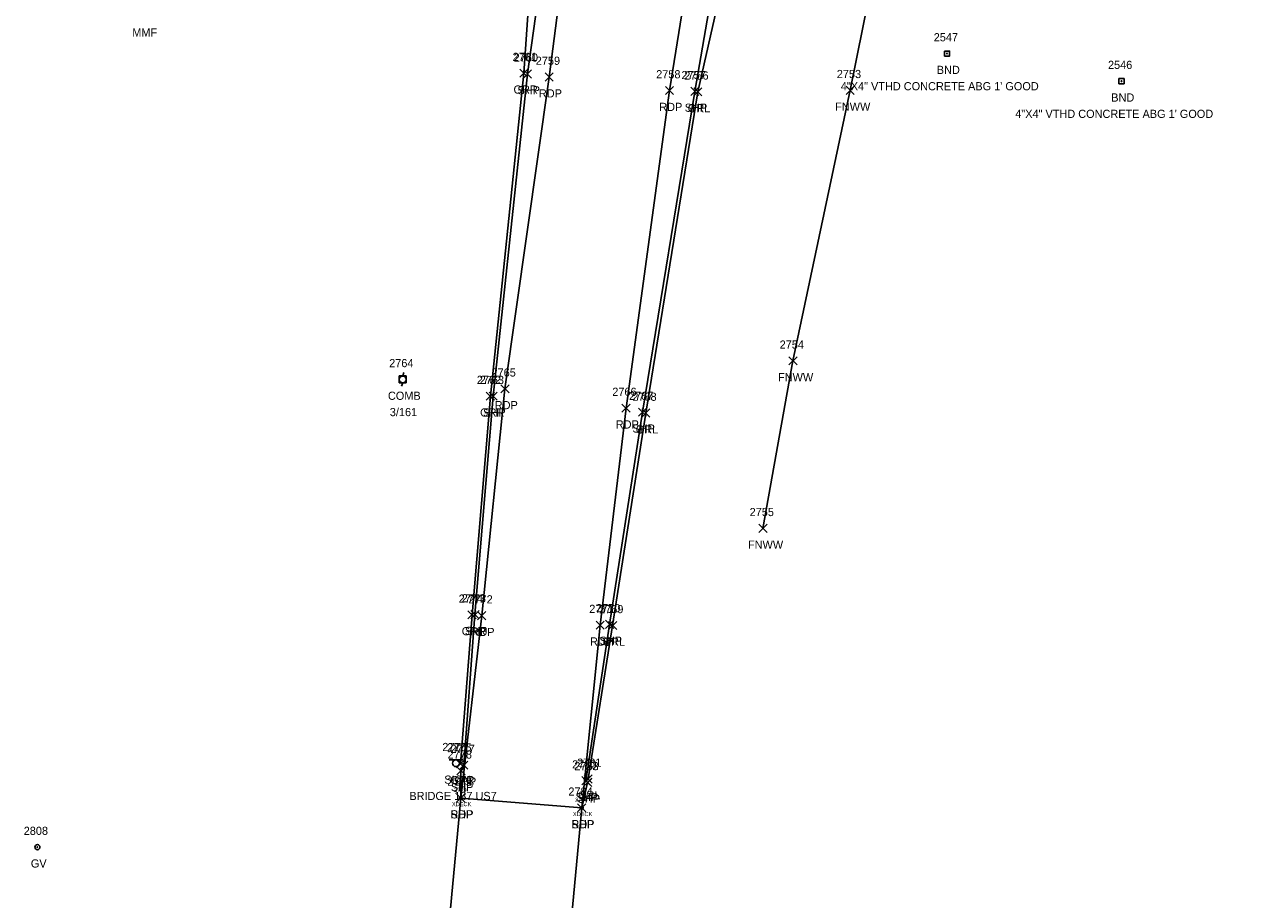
# Model space of a CAD drawing. Extents: x 1443071 to 1445292, y 614024 to 622563.
# Drawn here: x 1443936.5 to 1444233.7, y 619891.2 to 620105.8 of the extents above; entities that cross this region are included whole.
import ezdxf

# ---------------------------------------------------------------- set-up
doc = ezdxf.new("R2010")
doc.units = 0
for name, color, linetype in [('B_A', 7, 'Continuous'), ('B_I', 7, 'Continuous'), ('B_TIC', 7, 'Continuous'), ('BELB', 7, 'Continuous'), ('L_A', 7, 'Continuous'), ('L_I', 7, 'Continuous'), ('L_TIC', 7, 'Continuous'), ('LFNC', 7, 'Continuous'), ('M_A', 7, 'Continuous'), ('M_C', 7, 'Continuous'), ('M_I', 7, 'Continuous'), ('MHBP', 7, 'Continuous'), ('P_A', 7, 'Continuous'), ('P_I', 7, 'Continuous'), ('P_TIC', 7, 'Continuous'), ('PET', 7, 'Continuous'), ('PSP', 7, 'Continuous'), ('R_A', 7, 'Continuous'), ('R_I', 7, 'Continuous'), ('R_TIC', 7, 'Continuous'), ('RGR', 7, 'Continuous'), ('S_A', 7, 'Continuous'), ('S_C', 7, 'Continuous'), ('S_I', 7, 'Continuous'), ('SSGN', 7, 'Continuous'), ('U_A', 7, 'Continuous'), ('U_C', 7, 'Continuous'), ('U_I', 7, 'Continuous'), ('UP', 7, 'Continuous'), ('UWV', 7, 'Continuous')]:
    doc.layers.add(name, color=color, linetype=linetype)

msp = doc.modelspace()

# ---------------------------------------------------------------- linework, layer by layer
at = {"layer": 'B_TIC'}
for p, q in [((1444043.42, 619916.17), (1444043.5, 619916.17)), ((1444073.06, 619913.75), (1444073.13, 619913.75))]:
    msp.add_line(p, q, dxfattribs=at)
for points in [[(1444042.92, 619916.17), (1444043.92, 619916.17)], [(1444043.42, 619915.67), (1444043.42, 619916.67)], [(1444072.55, 619913.75), (1444073.55, 619913.75)], [(1444073.05, 619913.25), (1444073.05, 619914.25)]]:
    msp.add_lwpolyline(points, dxfattribs=at)
at = {"layer": 'BELB'}
for points in [[(1444043.42, 619916.17), (1444038.87, 619867.29), (1444033.97, 619808.54), (1444030.6, 619759.6)], [(1444073.05, 619913.75), (1444068.55, 619864.95), (1444063.61, 619806.17), (1444060.23, 619757.24)]]:
    msp.add_lwpolyline(points, dxfattribs=at)
at = {"layer": 'L_TIC'}
for points in [[(1444137.8, 620088.58), (1444139.8, 620090.58)], [(1444139.8, 620088.58), (1444137.8, 620090.58)], [(1444123.8, 620022.28), (1444125.8, 620024.28)], [(1444125.8, 620022.28), (1444123.8, 620024.28)], [(1444116.45, 619981.25), (1444118.45, 619983.25)], [(1444118.45, 619981.25), (1444116.45, 619983.25)]]:
    msp.add_lwpolyline(points, dxfattribs=at)
at = {"layer": 'LFNC'}
msp.add_lwpolyline([(1444167.73, 620231.87), (1444148.34, 620136.96), (1444138.8, 620089.58), (1444124.8, 620023.28), (1444117.45, 619982.25)], dxfattribs=at)
at = {"layer": 'MHBP'}
for points in [[(1444161.92, 620099.21), (1444163.17, 620099.21), (1444163.17, 620097.96), (1444161.92, 620097.96)], [(1444204.65, 620092.44), (1444205.9, 620092.44), (1444205.9, 620091.19), (1444204.65, 620091.19)]]:
    msp.add_lwpolyline(points, close=True, dxfattribs=at)
for centre in [(1444162.54, 620098.59), (1444205.27, 620091.82)]:
    msp.add_circle(centre, 0.0833, dxfattribs=at)
at = {"layer": 'P_TIC'}
for points in [[(1444058.79, 620092.6), (1444060.79, 620094.6)], [(1444060.79, 620092.6), (1444058.79, 620094.6)], [(1444064.08, 620091.83), (1444066.08, 620093.83)], [(1444066.08, 620091.83), (1444064.08, 620093.83)], [(1444093.56, 620088.52), (1444095.56, 620090.52)], [(1444095.56, 620088.52), (1444093.56, 620090.52)], [(1444099.76, 620088.32), (1444101.76, 620090.32)], [(1444101.76, 620088.32), (1444099.76, 620090.32)], [(1444053.27, 620015.44), (1444055.27, 620017.44)], [(1444055.27, 620015.44), (1444053.27, 620017.44)], [(1444050.39, 620013.62), (1444052.39, 620015.62)], [(1444052.39, 620013.62), (1444050.39, 620015.62)], [(1444082.91, 620010.71), (1444084.91, 620012.71)], [(1444084.91, 620010.71), (1444082.91, 620012.71)], [(1444086.94, 620009.71), (1444088.94, 620011.71)], [(1444088.94, 620009.71), (1444086.94, 620011.71)], [(1444045.92, 619960.11), (1444047.92, 619962.11)], [(1444047.92, 619960.11), (1444045.92, 619962.11)], [(1444047.57, 619959.86), (1444049.57, 619961.86)], [(1444049.57, 619959.86), (1444047.57, 619961.86)], [(1444076.6, 619957.52), (1444078.6, 619959.52)], [(1444078.6, 619957.52), (1444076.6, 619959.52)], [(1444078.9, 619957.71), (1444080.9, 619959.71)], [(1444080.9, 619957.71), (1444078.9, 619959.71)], [(1444042.48, 619921.84), (1444044.48, 619923.84)], [(1444044.48, 619921.84), (1444042.48, 619923.84)], [(1444043.18, 619923.22), (1444045.18, 619925.22)], [(1444045.18, 619923.22), (1444043.18, 619925.22)], [(1444073.06, 619919.41), (1444075.06, 619921.41)], [(1444075.06, 619919.41), (1444073.06, 619921.41)], [(1444073.5, 619919), (1444075.5, 619921)], [(1444075.5, 619919), (1444073.5, 619921)], [(1444073.51, 619918.99), (1444075.51, 619920.99)], [(1444075.51, 619918.99), (1444073.51, 619920.99)], [(1444042.42, 619915.17), (1444044.42, 619917.17)], [(1444044.42, 619915.17), (1444042.42, 619917.17)], [(1444042.42, 619915.17), (1444044.42, 619917.17)], [(1444044.42, 619915.17), (1444042.42, 619917.17)], [(1444072.05, 619912.75), (1444074.05, 619914.75)], [(1444074.05, 619912.75), (1444072.05, 619914.75)], [(1444072.05, 619912.75), (1444074.05, 619914.75)], [(1444074.05, 619912.75), (1444072.05, 619914.75)], [(1444072.05, 619912.75), (1444074.05, 619914.75)], [(1444074.05, 619912.75), (1444072.05, 619914.75)]]:
    msp.add_lwpolyline(points, dxfattribs=at)
at = {"layer": 'PET'}
for points in [[(1444393.99, 621275.61), (1444360.23, 621155.32), (1444345.74, 621103.98), (1444299.41, 620941.8), (1444273.27, 620844.52), (1444244.09, 620730.97), (1444221.37, 620651.37), (1444196.75, 620548.06), (1444177.44, 620486.23), (1444161.6, 620423.84), (1444143.45, 620356.38), (1444122.97, 620254.68), (1444105.94, 620160.17), (1444094.56, 620089.52), (1444083.91, 620011.71), (1444077.6, 619958.52), (1444073.05, 619913.75)], [(1444350.41, 621238.76), (1444319.14, 621126.97), (1444291.55, 621028.33), (1444258.02, 620908.98), (1444225.45, 620794.19), (1444210.22, 620737.59), (1444176.75, 620619.09), (1444153.1, 620523.45), (1444139.28, 620467.17), (1444131.97, 620435.45), (1444113.12, 620363.38), (1444103.37, 620315.76), (1444093.47, 620268.1), (1444084.86, 620222.29), (1444073.72, 620159.9), (1444065.08, 620092.83), (1444054.27, 620016.44), (1444048.57, 619960.86), (1444043.42, 619916.17), (1444073.05, 619913.75)]]:
    msp.add_lwpolyline(points, dxfattribs=at)
at = {"layer": 'PSP'}
for points in [[(1444228.91, 620648.98), (1444202.76, 620547.52), (1444186.16, 620483.96), (1444170.45, 620422.38), (1444153.07, 620354.47), (1444132.16, 620257.26), (1444128.32, 620238.3), (1444112.75, 620158.8), (1444100.76, 620089.32), (1444087.94, 620010.71), (1444079.9, 619958.71), (1444074.06, 619920.41), (1444074.5, 619920), (1444074.51, 619919.99), (1444073.05, 619913.75)], [(1444173.15, 620620.17), (1444162.97, 620582.35), (1444145.76, 620516.18), (1444133.67, 620469.15), (1444125.56, 620436.17), (1444114.52, 620389.82), (1444108.73, 620364.47), (1444098.18, 620317.14), (1444089.01, 620271.12), (1444079.56, 620223.77), (1444069.05, 620160.45), (1444059.79, 620093.6), (1444051.39, 620014.62), (1444046.92, 619961.11), (1444044.18, 619924.22), (1444043.48, 619922.84), (1444043.42, 619916.17)]]:
    msp.add_lwpolyline(points, dxfattribs=at)
at = {"layer": 'R_TIC'}
for points in [[(1444057.87, 620092.77), (1444059.87, 620094.77)], [(1444059.87, 620092.77), (1444057.87, 620094.77)], [(1444100.49, 620088.2), (1444102.49, 620090.2)], [(1444102.49, 620088.2), (1444100.49, 620090.2)], [(1444049.68, 620013.64), (1444051.68, 620015.64)], [(1444051.68, 620013.64), (1444049.68, 620015.64)], [(1444087.76, 620009.5), (1444089.76, 620011.5)], [(1444089.76, 620009.5), (1444087.76, 620011.5)], [(1444045.19, 619960.04), (1444047.19, 619962.04)], [(1444047.19, 619960.04), (1444045.19, 619962.04)], [(1444079.64, 619957.46), (1444081.64, 619959.46)], [(1444081.64, 619957.46), (1444079.64, 619959.46)], [(1444042.36, 619923.56), (1444044.36, 619925.56)], [(1444044.36, 619923.56), (1444042.36, 619925.56)], [(1444073.63, 619919.83), (1444075.63, 619921.83)], [(1444075.63, 619919.83), (1444073.63, 619921.83)]]:
    msp.add_lwpolyline(points, dxfattribs=at)
at = {"layer": 'RGR'}
for points in [[(1444116.85, 620157.19), (1444101.49, 620089.2), (1444088.76, 620010.5), (1444080.64, 619958.46), (1444074.63, 619920.83)], [(1444062.71, 620149.53), (1444058.87, 620093.77), (1444050.68, 620014.64), (1444046.19, 619961.04), (1444043.36, 619924.56)]]:
    msp.add_lwpolyline(points, dxfattribs=at)
at = {"layer": 'SSGN'}
for p, q in [((1444040.61, 619925.53), (1444043.95, 619925.53)), ((1444042.26, 619924.69), (1444042.26, 619924.69))]:
    msp.add_line(p, q, dxfattribs=at)
msp.add_circle((1444042.26, 619924.69), 0.833, dxfattribs=at)
at = {"layer": 'UP'}
for p, q in [((1444028.38, 620017.91), (1444028.38, 620019.58)), ((1444028.38, 620019.58), (1444030.04, 620019.58)), ((1444029.46, 620020.41), (1444029.21, 620019.58)), ((1444030.04, 620019.58), (1444030.04, 620017.91)), ((1444030.04, 620017.91), (1444028.38, 620017.91)), ((1444028.96, 620017.08), (1444029.21, 620017.91)), ((1444029.21, 620018.74), (1444029.21, 620018.74))]:
    msp.add_line(p, q, dxfattribs=at)
msp.add_circle((1444029.21, 620018.74), 0.833, dxfattribs=at)
at = {"layer": 'UWV'}
for radius in [0.625, 0.0833]:
    msp.add_circle((1443939.73, 619904.13), radius, dxfattribs=at)

# ---------------------------------------------------------------- texts
at = {"layer": 'B_A'}
for p in [(1444041.26, 619914.17), (1444070.9, 619911.75)]:
    msp.add_text('XDECK', height=1, dxfattribs=at).set_placement(p)
at = {"layer": 'B_I'}
for s, p in [('2779', (1444041.79, 619917.67)), ('2784', (1444071.42, 619915.25))]:
    msp.add_text(s, height=1, dxfattribs=at).set_placement(p)
at = {"layer": 'L_A'}
for s, p in [('MMF', (1443962.98, 620102.77)), ('FNWW', (1444135.14, 620084.58)), ('FNWW', (1444121.15, 620018.28)), ('FNWW', (1444113.79, 619977.25))]:
    msp.add_text(s, height=2, dxfattribs=at).set_placement(p)
at = {"layer": 'L_I'}
for s, p in [('2753', (1444135.54, 620092.58)), ('2754', (1444121.54, 620026.28)), ('2755', (1444114.19, 619985.25))]:
    msp.add_text(s, height=2, dxfattribs=at).set_placement(p)
at = {"layer": 'M_A'}
for p in [(1444160.03, 620093.59), (1444202.76, 620086.82)]:
    msp.add_text('BND', height=2, dxfattribs=at).set_placement(p)
at = {"layer": 'M_C'}
for p in [(1444136.52, 620089.59), (1444179.25, 620082.82)]:
    msp.add_text('4"X4" VTHD CONCRETE ABG 1\' GOOD', height=2, dxfattribs=at).set_placement(p)
at = {"layer": 'M_I'}
for s, p in [('2547', (1444159.28, 620101.59)), ('2546', (1444201.96, 620094.82))]:
    msp.add_text(s, height=2, dxfattribs=at).set_placement(p)
at = {"layer": 'P_A'}
for s, p in [('SHP', (1444057.33, 620088.6)), ('RDP', (1444062.57, 620087.83)), ('RDP', (1444092.05, 620084.52)), ('SHP', (1444098.3, 620084.32)), ('RDP', (1444051.76, 620011.44)), ('SHP', (1444048.93, 620009.62)), ('RDP', (1444081.4, 620006.71)), ('SHP', (1444085.48, 620005.71)), ('SHP', (1444044.46, 619956.11)), ('RDP', (1444046.06, 619955.86)), ('RDP', (1444075.09, 619953.52)), ('SHP', (1444077.44, 619953.71)), ('SHP', (1444041.72, 619919.22)), ('SHP', (1444041.02, 619917.84)), ('SHP', (1444071.59, 619915.41)), ('SHP', (1444072.04, 619915)), ('SHP', (1444072.04, 619914.99)), ('SHP', (1444040.95, 619911.17)), ('RDP', (1444040.91, 619911.17)), ('SHP', (1444070.59, 619908.75)), ('RDP', (1444070.54, 619908.75)), ('RDP', (1444070.54, 619908.75))]:
    msp.add_text(s, height=2, dxfattribs=at).set_placement(p)
at = {"layer": 'P_I'}
for s, p in [('2760', (1444056.4, 620096.6)), ('2759', (1444061.81, 620095.83)), ('2758', (1444091.3, 620092.52)), ('2757', (1444097.5, 620092.32)), ('2763', (1444048.08, 620017.62)), ('2765', (1444050.97, 620019.44)), ('2766', (1444080.55, 620014.71)), ('2767', (1444084.64, 620013.71)), ('2773', (1444043.66, 619964.11)), ('2772', (1444045.31, 619963.86)), ('2771', (1444074.91, 619961.52)), ('2770', (1444076.56, 619961.71)), ('2778', (1444040.22, 619925.84)), ('2777', (1444040.92, 619927.22)), ('2780', (1444070.71, 619923.41)), ('2782', (1444071.24, 619923)), ('2783', (1444071.25, 619922.99)), ('2779', (1444040.15, 619919.17)), ('2779', (1444040.15, 619919.17)), ('2784', (1444069.79, 619916.75)), ('2784', (1444069.79, 619916.75)), ('2784', (1444069.79, 619916.75))]:
    msp.add_text(s, height=2, dxfattribs=at).set_placement(p)
at = {"layer": 'R_A'}
for s, p in [('GRR', (1444056.36, 620088.77)), ('GRL', (1444099.04, 620084.2)), ('GRR', (1444048.17, 620009.64)), ('GRL', (1444086.3, 620005.5)), ('GRR', (1444043.68, 619956.04)), ('GRL', (1444078.18, 619953.46)), ('GRR', (1444040.85, 619919.56)), ('GRL', (1444072.17, 619915.83))]:
    msp.add_text(s, height=2, dxfattribs=at).set_placement(p)
at = {"layer": 'R_I'}
for s, p in [('2761', (1444056.13, 620096.77)), ('2756', (1444098.18, 620092.2)), ('2762', (1444047.37, 620017.64)), ('2768', (1444085.45, 620013.5)), ('2774', (1444042.93, 619964.04)), ('2769', (1444077.32, 619961.46)), ('2775', (1444040.1, 619927.56)), ('2781', (1444071.93, 619923.83))]:
    msp.add_text(s, height=2, dxfattribs=at).set_placement(p)
at = {"layer": 'S_A'}
msp.add_text('SIGN', height=2, dxfattribs=at).set_placement((1444039.4, 619919.67))
at = {"layer": 'S_C'}
msp.add_text('BRIDGE 137 US7', height=2, dxfattribs=at).set_placement((1444030.84, 619915.67))
at = {"layer": 'S_I'}
msp.add_text('2776', height=2, dxfattribs=at).set_placement((1444038.92, 619927.67))
at = {"layer": 'U_A'}
for s, p in [('COMB', (1444025.6, 620013.74)), ('GV', (1443938.13, 619899.13))]:
    msp.add_text(s, height=2, dxfattribs=at).set_placement(p)
at = {"layer": 'U_C'}
msp.add_text('3/161', height=2, dxfattribs=at).set_placement((1444026.06, 620009.74))
at = {"layer": 'U_I'}
for s, p in [('2764', (1444025.9, 620021.74)), ('2808', (1443936.39, 619907.13))]:
    msp.add_text(s, height=2, dxfattribs=at).set_placement(p)

doc.saveas('drawing.dxf')
